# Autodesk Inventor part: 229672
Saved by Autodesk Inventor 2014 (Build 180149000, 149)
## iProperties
Shininess: 64.0
Length Units: 11272
Angle Units: 11279
Time Units: 11290
Mass Units: 11286
Length Display Precision: 3
Angle Display Precision: 2
Company: Autodesk, Inc.
Created: 2001-12
Part Number: 229672
Material: Stainless Steel, 440C
Description: FITTING; MC-G12-SS
Document SubType Name: Modeling
Designer: Autodesk, Inc.
Density: 7.75 g/cm^3
Mass: 152.747 g
Surface Area: 44.2522 cm^2
Volume: 19.7093 cm^3
Appearance: Stainless Steel
Density: 7.75
Volumn: 1.1899929784618444
Area: 7.049002142317107
PropertySet Name: Model Information
Control State: 0
Master: False
Checked Out: False
Last Check In By: JT
Last Check In Date: 2003-06-20
Title: FITTING; MC-G12-SS
Author: Autodesk, Inc.
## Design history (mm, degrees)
derived "MC-G.ipt"
body "Solid1"
tag "TaggingFeature2"
feature "Solid1::MC-G.ipt" dims "ScaleForDerivedMember" = 10
